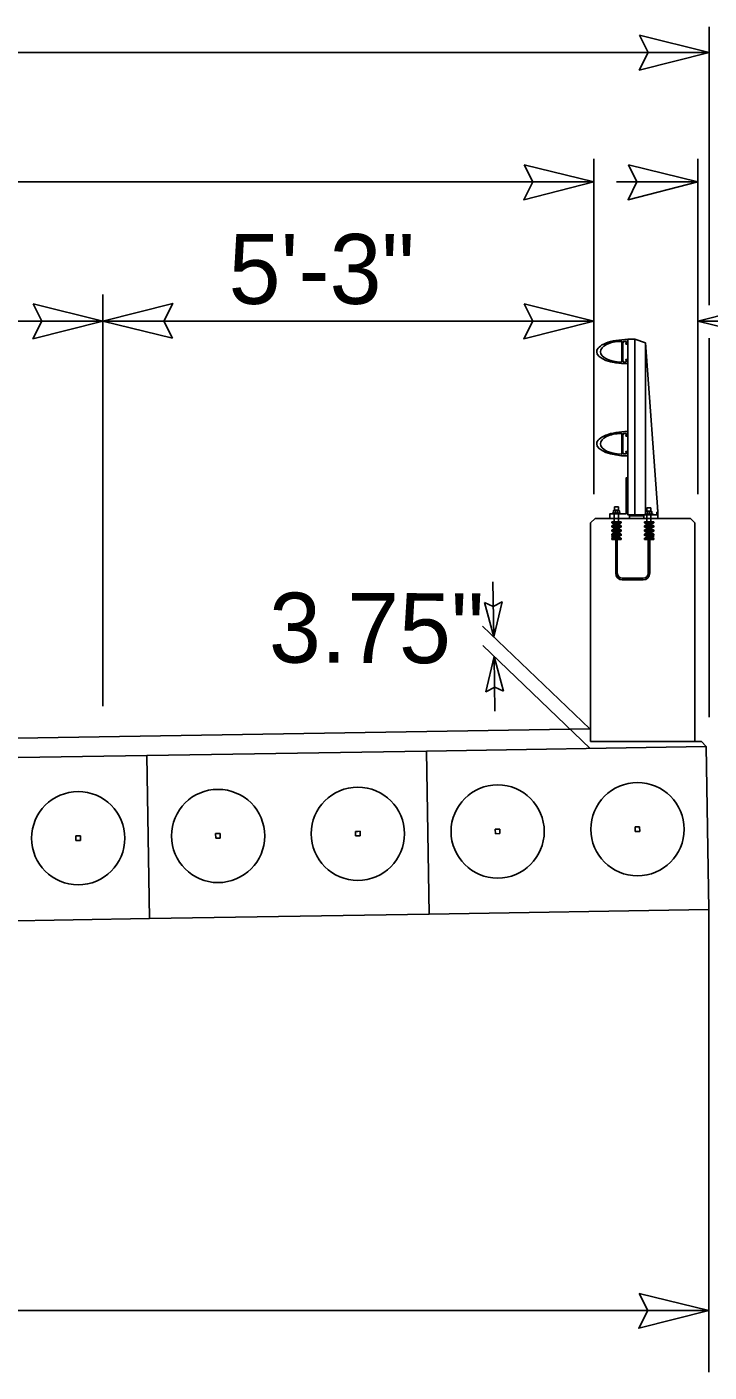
# Model space of a CAD drawing. Extents: x 573980 to 574178, y -53449 to -53334.
# Drawn here: x 574100.88 to 574110.03, y -53435.39 to -53417.36 of the extents above; entities that cross this region are included whole.
import ezdxf

# ---------------------------------------------------------------- set-up
doc = ezdxf.new("R2010")
doc.units = 0
for name, color, linetype in [('Old_Level_1', 7, 'Continuous'), ('Old_Level_11', 7, 'Continuous'), ('Prop Dimension Text', 7, 'Continuous'), ('Typical Bridge Rail Two Bar CELL', 7, 'Continuous'), ('Typical Terminator CELL', 7, 'Continuous')]:
    doc.layers.add(name, color=color, linetype=linetype)

# ---------------------------------------------------------------- blocks, each defined once
blk = doc.blocks.new('TERMINATOR')
at = {"layer": 'Typical Terminator CELL'}
blk.add_lwpolyline([(-0.4687, 0.0807), (0, 0), (-0.4713, -0.0833), (-0.4114, 0)], close=True, dxfattribs=at)

msp = doc.modelspace()

# ---------------------------------------------------------------- linework, layer by layer
at = {"layer": 'Old_Level_1'}
for p, q in [((574070.29, -53427.378), (574108.44, -53426.767)), ((574098.743, -53427.183), (574102.493, -53427.123)), ((574102.493, -53427.123), (574106.242, -53427.063)), ((574102.493, -53427.123), (574102.528, -53429.31)), ((574102.528, -53429.31), (574102.493, -53427.123)), ((574106.242, -53427.063), (574109.992, -53427.003)), ((574106.242, -53427.063), (574106.277, -53429.25)), ((574106.277, -53429.25), (574106.242, -53427.063)), ((574109.992, -53427.003), (574110.027, -53429.19)), ((574101.572, -53428.2), (574101.54, -53428.2)), ((574101.54, -53428.2), (574101.541, -53428.262)), ((574101.602, -53428.199), (574101.572, -53428.2)), ((574101.603, -53428.261), (574101.602, -53428.199)), ((574103.447, -53428.17), (574103.415, -53428.17)), ((574103.415, -53428.17), (574103.416, -53428.232)), ((574103.416, -53428.232), (574103.478, -53428.231)), ((574103.477, -53428.169), (574103.447, -53428.17)), ((574103.478, -53428.231), (574103.477, -53428.169)), ((574105.322, -53428.14), (574105.29, -53428.14)), ((574105.29, -53428.14), (574105.291, -53428.202)), ((574105.291, -53428.202), (574105.353, -53428.201)), ((574105.352, -53428.139), (574105.322, -53428.14)), ((574105.353, -53428.201), (574105.352, -53428.139)), ((574107.197, -53428.11), (574107.165, -53428.11)), ((574107.165, -53428.11), (574107.166, -53428.172)), ((574107.166, -53428.172), (574107.228, -53428.171)), ((574107.227, -53428.109), (574107.197, -53428.11)), ((574107.228, -53428.171), (574107.227, -53428.109)), ((574109.071, -53428.08), (574109.039, -53428.08)), ((574109.039, -53428.08), (574109.04, -53428.142)), ((574109.04, -53428.142), (574109.102, -53428.141)), ((574109.101, -53428.079), (574109.071, -53428.08)), ((574109.102, -53428.141), (574109.101, -53428.079)), ((574101.541, -53428.262), (574101.603, -53428.261)), ((574102.528, -53429.31), (574098.778, -53429.37)), ((574106.277, -53429.25), (574102.528, -53429.31)), ((574110.027, -53429.19), (574106.277, -53429.25))]:
    msp.add_line(p, q, dxfattribs=at)
for centre in [(574107.197, -53428.142), (574109.072, -53428.112), (574101.573, -53428.232), (574103.448, -53428.202), (574105.322, -53428.172)]:
    msp.add_circle(centre, 0.625, dxfattribs=at)
at = {"layer": 'Prop Dimension Text'}
for p, q in [((574110.032, -53421.084), (574110.032, -53417.355)), ((574068.782, -53417.697), (574110.032, -53417.697)), ((574108.485, -53423.619), (574108.485, -53419.126)), ((574109.882, -53423.619), (574109.882, -53419.126)), ((574070.33, -53419.434), (574108.485, -53419.434)), ((574108.79, -53419.434), (574109.882, -53419.434)), ((574101.903, -53426.461), (574101.903, -53420.943)), ((574070.33, -53421.299), (574108.485, -53421.299)), ((574109.882, -53421.299), (574113.622, -53421.299)), ((574110.032, -53426.609), (574110.032, -53421.527)), ((574107.145, -53425.534), (574107.133, -53424.797)), ((574108.432, -53426.768), (574106.993, -53425.388)), ((574108.436, -53427.029), (574106.997, -53425.649)), ((574107.16, -53426.528), (574107.149, -53425.798)), ((574110.027, -53429.19), (574110.027, -53435.39)), ((574110.027, -53434.565), (574089.403, -53434.565))]:
    msp.add_line(p, q, dxfattribs=at)
at = {"layer": 'Typical Bridge Rail Two Bar CELL'}
for p, q in [((574108.943, -53421.543), (574109.037, -53421.543)), ((574108.943, -53423.897), (574108.943, -53421.543)), ((574109.179, -53421.589), (574109.037, -53421.543)), ((574109.037, -53423.897), (574109.037, -53421.543)), ((574108.864, -53421.582), (574108.864, -53421.71)), ((574108.864, -53421.838), (574108.864, -53421.71)), ((574109.179, -53423.897), (574109.179, -53421.589)), ((574109.179, -53421.589), (574109.343, -53423.85)), ((574108.864, -53422.816), (574108.864, -53422.944)), ((574109.179, -53422.67), (574109.184, -53422.67)), ((574108.864, -53423.072), (574108.864, -53422.944)), ((574108.76, -53423.99), (574108.76, -53423.885)), ((574108.762, -53423.834), (574108.762, -53423.79)), ((574108.762, -53423.79), (574108.816, -53423.79)), ((574108.816, -53423.79), (574108.816, -53423.834)), ((574108.819, -53423.99), (574108.819, -53423.885)), ((574109.198, -53423.846), (574109.198, -53423.802)), ((574109.198, -53423.802), (574109.252, -53423.802)), ((574109.199, -53424.002), (574109.199, -53423.897)), ((574109.252, -53423.802), (574109.252, -53423.846)), ((574109.253, -53424.002), (574109.253, -53423.897)), ((574109.339, -53423.824), (574109.339, -53423.783)), ((574109.343, -53423.897), (574109.343, -53423.85)), ((574108.444, -53424.005), (574108.505, -53423.944)), ((574108.444, -53424.005), (574108.444, -53426.937)), ((574108.505, -53423.944), (574109.781, -53423.944)), ((574108.728, -53423.99), (574108.854, -53423.99)), ((574108.728, -53424.003), (574108.854, -53424.003)), ((574108.728, -53424.045), (574108.78, -53424.045)), ((574108.728, -53424.059), (574108.78, -53424.059)), ((574108.756, -53424.018), (574108.78, -53424.018)), ((574108.756, -53424.031), (574108.78, -53424.031)), ((574108.756, -53424.073), (574108.78, -53424.073)), ((574108.756, -53424.087), (574108.78, -53424.087)), ((574108.78, -53424.017), (574108.78, -53424.681)), ((574108.78, -53424.018), (574108.801, -53424.018)), ((574108.801, -53424.017), (574108.801, -53424.681)), ((574108.801, -53424.018), (574108.826, -53424.018)), ((574108.801, -53424.031), (574108.826, -53424.031)), ((574108.801, -53424.045), (574108.854, -53424.045)), ((574108.801, -53424.059), (574108.854, -53424.059)), ((574108.801, -53424.073), (574108.826, -53424.073)), ((574108.801, -53424.087), (574108.826, -53424.087)), ((574109.164, -53423.99), (574109.289, -53423.99)), ((574109.164, -53424.003), (574109.289, -53424.003)), ((574109.164, -53424.045), (574109.216, -53424.045)), ((574109.164, -53424.059), (574109.216, -53424.059)), ((574109.192, -53424.018), (574109.216, -53424.018)), ((574109.192, -53424.031), (574109.216, -53424.031)), ((574109.192, -53424.073), (574109.216, -53424.073)), ((574109.192, -53424.087), (574109.216, -53424.087)), ((574109.216, -53424.017), (574109.237, -53424.017)), ((574109.216, -53424.017), (574109.216, -53424.681)), ((574109.237, -53424.017), (574109.237, -53424.681)), ((574109.237, -53424.018), (574109.262, -53424.018)), ((574109.237, -53424.031), (574109.262, -53424.031)), ((574109.237, -53424.045), (574109.289, -53424.045)), ((574109.237, -53424.059), (574109.289, -53424.059)), ((574109.237, -53424.073), (574109.262, -53424.073)), ((574109.237, -53424.087), (574109.262, -53424.087)), ((574109.781, -53423.944), (574109.842, -53424.005)), ((574109.842, -53424.005), (574109.842, -53426.937)), ((574108.728, -53424.101), (574108.78, -53424.101)), ((574108.728, -53424.115), (574108.78, -53424.115)), ((574108.728, -53424.156), (574108.78, -53424.156)), ((574108.728, -53424.17), (574108.78, -53424.17)), ((574108.728, -53424.212), (574108.78, -53424.212)), ((574108.728, -53424.226), (574108.78, -53424.226)), ((574108.756, -53424.129), (574108.78, -53424.129)), ((574108.756, -53424.142), (574108.78, -53424.142)), ((574108.756, -53424.184), (574108.78, -53424.184)), ((574108.756, -53424.198), (574108.78, -53424.198)), ((574108.801, -53424.101), (574108.854, -53424.101)), ((574108.801, -53424.115), (574108.854, -53424.115)), ((574108.801, -53424.129), (574108.826, -53424.129)), ((574108.801, -53424.142), (574108.826, -53424.142)), ((574108.801, -53424.156), (574108.854, -53424.156)), ((574108.801, -53424.17), (574108.854, -53424.17)), ((574108.801, -53424.184), (574108.826, -53424.184)), ((574108.801, -53424.198), (574108.826, -53424.198)), ((574108.801, -53424.212), (574108.854, -53424.212)), ((574108.801, -53424.226), (574108.854, -53424.226)), ((574109.164, -53424.101), (574109.216, -53424.101)), ((574109.164, -53424.115), (574109.216, -53424.115)), ((574109.164, -53424.156), (574109.216, -53424.156)), ((574109.164, -53424.17), (574109.216, -53424.17)), ((574109.164, -53424.212), (574109.216, -53424.212)), ((574109.164, -53424.226), (574109.216, -53424.226)), ((574109.192, -53424.129), (574109.216, -53424.129)), ((574109.192, -53424.142), (574109.216, -53424.142)), ((574109.192, -53424.184), (574109.216, -53424.184)), ((574109.192, -53424.198), (574109.216, -53424.198)), ((574109.237, -53424.101), (574109.289, -53424.101)), ((574109.237, -53424.115), (574109.289, -53424.115)), ((574109.237, -53424.129), (574109.262, -53424.129)), ((574109.237, -53424.142), (574109.262, -53424.142)), ((574109.237, -53424.156), (574109.289, -53424.156)), ((574109.237, -53424.17), (574109.289, -53424.17)), ((574109.237, -53424.184), (574109.262, -53424.184)), ((574109.237, -53424.198), (574109.262, -53424.198)), ((574109.237, -53424.212), (574109.289, -53424.212)), ((574109.237, -53424.226), (574109.289, -53424.226)), ((574108.868, -53424.747), (574109.149, -53424.747)), ((574108.868, -53424.768), (574109.149, -53424.768)), ((574108.444, -53426.937), (574109.83, -53426.937)), ((574109.83, -53426.937), (574109.931, -53426.937)), ((574109.992, -53427.003), (574109.931, -53426.937))]:
    msp.add_line(p, q, dxfattribs=at)
for points in [[(574108.943, -53421.873), (574108.943, -53421.812), (574108.917, -53421.812), (574108.917, -53421.822), (574108.92, -53421.822), (574108.92, -53421.848), (574108.879, -53421.848), (574108.874, -53421.808), (574108.874, -53421.71), (574108.874, -53421.611), (574108.879, -53421.572), (574108.92, -53421.572), (574108.92, -53421.598), (574108.917, -53421.598), (574108.917, -53421.608), (574108.943, -53421.608), (574108.943, -53421.546)], [(574108.943, -53423.107), (574108.943, -53423.046), (574108.917, -53423.046), (574108.917, -53423.056), (574108.92, -53423.056), (574108.92, -53423.081), (574108.879, -53423.081), (574108.874, -53423.042), (574108.874, -53422.944), (574108.874, -53422.845), (574108.879, -53422.806), (574108.92, -53422.806), (574108.92, -53422.831), (574108.917, -53422.831), (574108.917, -53422.842), (574108.943, -53422.842), (574108.943, -53422.781)], [(574108.701, -53423.944), (574108.701, -53423.885), (574108.919, -53423.885), (574108.919, -53423.402), (574108.943, -53423.402), (574108.943, -53423.897), (574109.332, -53423.897), (574109.332, -53423.863), (574109.343, -53423.863), (574109.343, -53423.944), (574109.156, -53423.944), (574109.156, -53423.912), (574108.966, -53423.912), (574108.966, -53423.944), (574108.701, -53423.944)], [(574108.734, -53423.886), (574108.734, -53423.875), (574108.788, -53423.875), (574108.842, -53423.875), (574108.842, -53423.886)], [(574108.749, -53423.876), (574108.749, -53423.841), (574108.756, -53423.835), (574108.822, -53423.835), (574108.829, -53423.841), (574108.829, -53423.876), (574108.749, -53423.876), (574108.776, -53423.876), (574108.776, -53423.841), (574108.769, -53423.835), (574108.776, -53423.841), (574108.782, -53423.835), (574108.796, -53423.835), (574108.802, -53423.841), (574108.802, -53423.876), (574108.802, -53423.841), (574108.809, -53423.835)], [(574109.172, -53423.898), (574109.172, -53423.887), (574109.225, -53423.887), (574109.279, -53423.887), (574109.279, -53423.898)], [(574109.186, -53423.887), (574109.186, -53423.853), (574109.192, -53423.846), (574109.258, -53423.846), (574109.265, -53423.853), (574109.265, -53423.887), (574109.186, -53423.887), (574109.212, -53423.887), (574109.212, -53423.853), (574109.205, -53423.846), (574109.212, -53423.853), (574109.218, -53423.846), (574109.232, -53423.846), (574109.239, -53423.853), (574109.239, -53423.887), (574109.239, -53423.853), (574109.245, -53423.846)], [(574108.728, -53423.99), (574108.728, -53424.003), (574108.756, -53424.018), (574108.756, -53424.031), (574108.728, -53424.045), (574108.728, -53424.059), (574108.756, -53424.073), (574108.756, -53424.087), (574108.728, -53424.101), (574108.728, -53424.115), (574108.756, -53424.129), (574108.756, -53424.142), (574108.728, -53424.156), (574108.728, -53424.17), (574108.756, -53424.184), (574108.756, -53424.198), (574108.728, -53424.212), (574108.728, -53424.226)], [(574108.854, -53423.99), (574108.854, -53424.003), (574108.826, -53424.018), (574108.826, -53424.031), (574108.854, -53424.045), (574108.854, -53424.059), (574108.826, -53424.073), (574108.826, -53424.087), (574108.854, -53424.101), (574108.854, -53424.115), (574108.826, -53424.129), (574108.826, -53424.142), (574108.854, -53424.156), (574108.854, -53424.17), (574108.826, -53424.184), (574108.826, -53424.198), (574108.854, -53424.212), (574108.854, -53424.226)], [(574109.164, -53423.99), (574109.164, -53424.003), (574109.191, -53424.018), (574109.191, -53424.031), (574109.164, -53424.045), (574109.164, -53424.059), (574109.191, -53424.073), (574109.191, -53424.087), (574109.164, -53424.101), (574109.164, -53424.115), (574109.191, -53424.129), (574109.191, -53424.142), (574109.164, -53424.156), (574109.164, -53424.17), (574109.191, -53424.184), (574109.191, -53424.198), (574109.164, -53424.212), (574109.164, -53424.226)], [(574109.289, -53423.99), (574109.289, -53424.003), (574109.262, -53424.018), (574109.262, -53424.031), (574109.289, -53424.045), (574109.289, -53424.059), (574109.262, -53424.073), (574109.262, -53424.087), (574109.289, -53424.101), (574109.289, -53424.115), (574109.262, -53424.129), (574109.262, -53424.142), (574109.289, -53424.156), (574109.289, -53424.17), (574109.262, -53424.184), (574109.262, -53424.198), (574109.289, -53424.212), (574109.289, -53424.226)]]:
    msp.add_lwpolyline(points, dxfattribs=at)
for centre in [(574108.739, -53424.191), (574109.278, -53424.191)]:
    msp.add_circle(centre, 0.0104, dxfattribs=at)
for centre, radius, start, end in [((574108.854, -53421.582), 0.00979, 360, 90), ((574108.854, -53421.838), 0.00979, 270, 360), ((574108.854, -53422.816), 0.00979, 360, 90), ((574108.854, -53423.072), 0.00979, 270, 360), ((574108.868, -53424.681), 0.0876, 180, 270), ((574108.868, -53424.681), 0.0667, 180, 270), ((574109.149, -53424.681), 0.0667, 270, 360), ((574109.149, -53424.681), 0.0876, 270, 360)]:
    msp.add_arc(centre, radius, start, end, dxfattribs=at)
for centre, major_axis, ratio, start_param, end_param in [((574108.943, -53421.71), (-0.418, 0), 0.39036, 4.712404, 6.283584), ((574108.854, -53421.71), (-0.278, 0), 0.495501, 4.712489, 6.283652), ((574108.943, -53421.71), (-0.418, 0), 0.39036, 0.000398, 1.570782), ((574108.854, -53421.71), (-0.278, 0), 0.495501, 0.000467, 1.570696), ((574108.943, -53422.944), (-0.418, 0), 0.39036, 4.712404, 6.283584), ((574108.854, -53422.944), (-0.278, 0), 0.495501, 4.712489, 6.283652), ((574108.943, -53422.944), (-0.418, 0), 0.39036, 0.000398, 1.570782), ((574108.854, -53422.944), (-0.278, 0), 0.495501, 0.000467, 1.570696)]:
    msp.add_ellipse(centre, major_axis=major_axis, ratio=ratio, start_param=start_param, end_param=end_param, dxfattribs=at)

# ---------------------------------------------------------------- block references
at = {"layer": 'Old_Level_11'}
for p, xscale, yscale, rotation in [((574110.032, -53417.697), 1.9883351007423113, 2.8538812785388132, -2.3029191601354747e-10), ((574108.485, -53419.434), 1.9883351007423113, 2.8538812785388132, -2.3029191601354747e-10), ((574109.882, -53419.434), 1.9883351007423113, 2.8538812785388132, -2.3029191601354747e-10), ((574101.903, -53421.299), 1.9883351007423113, 2.8538812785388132, -2.3029191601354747e-10), ((574101.903, -53421.299), 1.9883351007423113, 2.8538812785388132, 179.9999999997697), ((574108.485, -53421.299), 1.9883351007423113, 2.8538812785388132, -2.3029191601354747e-10), ((574109.882, -53421.299), 1.9883351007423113, 2.8538812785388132, 179.9999999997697), ((574107.145, -53425.534), 0.9941675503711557, -1.4269406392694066, -89.08334574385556), ((574107.149, -53425.798), 0.9941675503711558, -1.4269406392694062, 91.15959340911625), ((574110.027, -53434.565), 1.9883351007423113, 2.8538812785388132, -2.3029191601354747e-10)]:
    msp.add_blockref('TERMINATOR', p, dxfattribs=dict(at, xscale=xscale, yscale=yscale, rotation=rotation))

# ---------------------------------------------------------------- texts
at = {"layer": 'Prop Dimension Text'}
for s, rotation, p in [('5\'-3"', 360, (574103.589, -53421.069)), ('3.75"', 359.7854, (574104.129, -53425.877))]:
    msp.add_text(s, height=0.9375, rotation=rotation, dxfattribs=at).set_placement(p)

doc.saveas('drawing.dxf')
